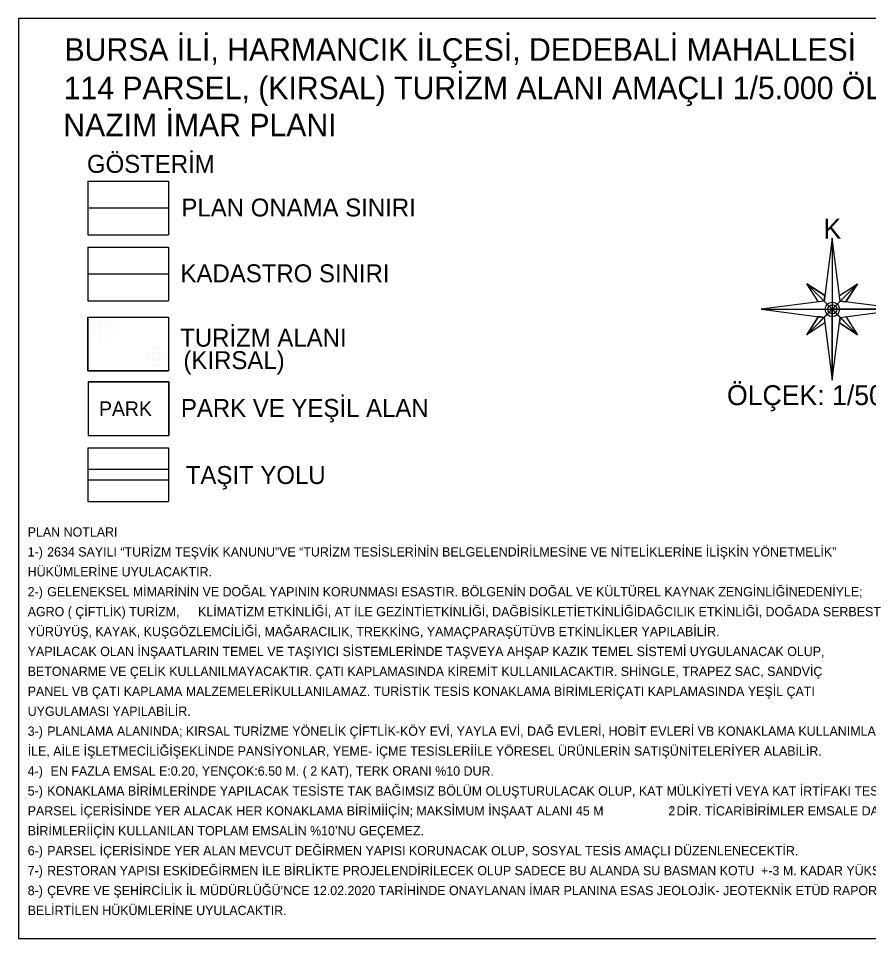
# Model space of a CAD drawing. Extents: x 415376 to 421084, y 4391163 to 4393878.
# Drawn here: x 416870 to 417511, y 4392614 to 4393307 of the extents above; entities that cross this region are included whole.
import ezdxf

# ---------------------------------------------------------------- set-up
doc = ezdxf.new("R2010")
doc.units = 0
for name, color, linetype in [('KALDIRIM', 7, 'Continuous'), ('LEJAND', 7, 'Continuous'), ('PL_KiRSALTURIZM', 7, 'Continuous'), ('PL_PARK', 7, 'Continuous'), ('SN_PLAN_ONAMA', 7, 'Continuous'), ('TR_TURIZM', 7, 'Continuous'), ('Z_PARSEL_PL', 7, 'Continuous')]:
    doc.layers.add(name, color=color, linetype=linetype)

msp = doc.modelspace()

# ---------------------------------------------------------------- linework, layer by layer
at = {"layer": 'KALDIRIM'}
for p, q in [((416922.79, 4392967.19), (416938.59, 4392967.19)), ((416938.59, 4392967.19), (416983.35, 4392967.19)), ((416922.79, 4392959.19), (416939.04, 4392959.19)), ((416939.04, 4392959.19), (416983.35, 4392959.19))]:
    msp.add_line(p, q, dxfattribs=at)
at = {"layer": 'LEJAND'}
for p, q in [((417672.31, 4393306.66), (416870.43, 4393306.66)), ((416870.43, 4393306.66), (416870.43, 4392613.77)), ((416922.79, 4393184.05), (416922.79, 4393143.6)), ((416922.79, 4393184.05), (416983.46, 4393184.05)), ((416983.46, 4393184.05), (416983.46, 4393143.6)), ((416922.79, 4393143.6), (416983.46, 4393143.6)), ((417483.55, 4393141.18), (417483.55, 4393087.66)), ((417483.99, 4393141.76), (417483.99, 4393141.65)), ((416922.79, 4393134.44), (416983.46, 4393134.44)), ((416922.79, 4393134.44), (416922.79, 4393093.99)), ((416983.46, 4393134.44), (416983.46, 4393093.99)), ((417483.55, 4393087.66), (417464.38, 4393106.82)), ((417483.55, 4393087.66), (417502.71, 4393106.82)), ((416922.79, 4393093.99), (416983.46, 4393093.99)), ((417430.02, 4393087.66), (417483.55, 4393087.66)), ((417483.55, 4393087.66), (417464.38, 4393068.5)), ((417483.55, 4393087.66), (417483.55, 4393034.14)), ((417483.55, 4393087.66), (417502.71, 4393068.5)), ((417483.55, 4393087.66), (417537.07, 4393087.66)), ((416922.79, 4393081.78), (416922.79, 4393041.34)), ((416922.79, 4393081.78), (416983.46, 4393081.78)), ((416983.46, 4393081.78), (416983.46, 4393041.34)), ((416922.79, 4393041.34), (416983.46, 4393041.34)), ((416923.11, 4393033.04), (416923.11, 4392992.6)), ((416923.11, 4393033.04), (416983.78, 4393033.04)), ((416983.78, 4393033.04), (416983.78, 4392992.6)), ((416923.11, 4392992.6), (416983.78, 4392992.6)), ((416922.79, 4392983.38), (416922.79, 4392942.93)), ((416922.79, 4392983.38), (416983.46, 4392983.38)), ((416983.46, 4392983.38), (416983.46, 4392942.93)), ((416922.79, 4392942.93), (416983.46, 4392942.93)), ((416870.43, 4392613.77), (417672.31, 4392613.77))]:
    msp.add_line(p, q, dxfattribs=at)
for points in [[(417489.64, 4393093.76), (417483.55, 4393141.18), (417477.45, 4393093.76), (417430.02, 4393087.66), (417477.45, 4393081.56), (417483.55, 4393034.14), (417489.64, 4393081.56), (417537.07, 4393087.66)], [(417483.55, 4393141.18), (417483.55, 4393087.66), (417489.64, 4393093.76)], [(417464.38, 4393106.82), (417477.45, 4393093.76), (417477.99, 4393098)], [(417489.64, 4393093.76), (417493.89, 4393093.21), (417502.71, 4393106.82)], [(417477.45, 4393093.76), (417430.07, 4393087.66), (417483.55, 4393087.66)], [(417483.55, 4393087.66), (417477.45, 4393081.56), (417483.55, 4393034.14)], [(417483.55, 4393087.66), (417489.64, 4393081.56), (417537.07, 4393087.66)], [(417473.2, 4393082.11), (417464.38, 4393068.5), (417477.45, 4393081.56)], [(417489.64, 4393081.56), (417489.1, 4393077.32), (417502.71, 4393068.5)]]:
    msp.add_lwpolyline(points, close=True, dxfattribs=at)
for points in [[(417473.2, 4393093.21), (417464.38, 4393106.82), (417477.99, 4393098)], [(417489.1, 4393098), (417502.71, 4393106.82), (417493.89, 4393093.21)], [(417477.99, 4393077.32), (417464.38, 4393068.5), (417473.2, 4393082.11)], [(417493.89, 4393082.11), (417502.71, 4393068.5), (417489.1, 4393077.32)]]:
    msp.add_lwpolyline(points, dxfattribs=at)
for centre, radius in [((417483.64, 4393087.53), 5.42), ((417483.73, 4393087.62), 3.39)]:
    msp.add_circle(centre, radius, dxfattribs=at)
at = {"layer": 'PL_KiRSALTURIZM'}
msp.add_lwpolyline([(416983.46, 4393081.78), (416983.46, 4393041.34), (416922.79, 4393041.34), (416922.79, 4393081.78)], close=True, dxfattribs=at)
at = {"layer": 'PL_PARK'}
msp.add_lwpolyline([(416983.78, 4393033.04), (416923.11, 4393033.04), (416923.11, 4392992.6), (416983.78, 4392992.6), (416983.78, 4393033.04)], dxfattribs=at)
at = {"layer": 'SN_PLAN_ONAMA'}
msp.add_line((416923.8, 4393164.06), (416983.11, 4393164.06), dxfattribs=at)
at = {"layer": 'TR_TURIZM'}
for p, q in [((416932.06, 4393079.11), (416932.06, 4393079.11)), ((416936.56, 4393079.11), (416936.56, 4393079.11)), ((416927.56, 4393074.61), (416927.56, 4393074.61)), ((416932.06, 4393074.61), (416932.06, 4393074.61)), ((416936.56, 4393074.61), (416936.56, 4393074.61)), ((416941.06, 4393074.61), (416941.06, 4393074.61)), ((416927.56, 4393070.11), (416927.56, 4393070.11)), ((416932.06, 4393070.11), (416932.06, 4393070.11)), ((416932.06, 4393065.61), (416932.06, 4393065.61)), ((416936.56, 4393070.11), (416936.56, 4393070.11)), ((416936.56, 4393065.61), (416936.56, 4393065.61)), ((416941.06, 4393070.11), (416941.06, 4393070.11)), ((416972.48, 4393058.55), (416972.48, 4393058.55)), ((416976.98, 4393058.55), (416976.98, 4393058.55)), ((416967.98, 4393054.05), (416967.98, 4393054.05)), ((416972.48, 4393054.05), (416972.48, 4393054.05)), ((416976.98, 4393054.05), (416976.98, 4393054.05)), ((416981.48, 4393054.05), (416981.48, 4393054.05)), ((416967.98, 4393049.55), (416967.98, 4393049.55)), ((416972.48, 4393049.55), (416972.48, 4393049.55)), ((416972.48, 4393045.05), (416972.48, 4393045.05)), ((416976.98, 4393049.55), (416976.98, 4393049.55)), ((416976.98, 4393045.05), (416976.98, 4393045.05)), ((416981.48, 4393049.55), (416981.48, 4393049.55))]:
    msp.add_line(p, q, dxfattribs=at)
at = {"layer": 'Z_PARSEL_PL'}
msp.add_line((416922.79, 4393114.22), (416983.46, 4393114.22), dxfattribs=at)

# ---------------------------------------------------------------- texts
at = {"layer": 'LEJAND'}
for s, height, p in [('BURSA İLİ, HARMANCIK İLÇESİ, DEDEBALİ MAHALLESİ', 17, (416905.18, 4393274.75)), ('114 PARSEL, (KIRSAL) TURİZM ALANI AMAÇLI 1/5.000 ÖLÇEKLİ', 17, (416904.57, 4393245.84)), ('NAZIM İMAR PLANI', 17, (416904.28, 4393217.87)), ('GÖSTERİM', 13.5, (416922.08, 4393190.37)), ('PLAN ONAMA SINIRI', 13.5, (416993.26, 4393157.51)), ('K', 15, (417476.88, 4393140.88)), ('KADASTRO SINIRI ', 13.5, (416992.56, 4393107.97)), ('TURİZM ALANI', 13.5, (416992.33, 4393059.51)), ('(KIRSAL)', 13.5, (416994.78, 4393042.58)), ('ÖLÇEK: 1/5000', 15, (417404.26, 4393015.45)), ('PARK VE YEŞİL ALAN', 13.5, (416992.88, 4393006.57)), ('PARK', 10.935, (416931.17, 4393007.33)), ('TAŞIT YOLU', 13.5, (416996.56, 4392956.08)), ('PLAN NOTLARI', 7, (416877.44, 4392916.48)), ('1-) ', 7, (416877.44, 4392901.48)), ('2634 SAYILI “TURİZM TEŞVİK KANUNU”VE “TURİZM TESİSLERİNİN BELGELENDİRİLMESİNE VE NİTELİKLERİNE İLİŞKİN YÖNETMELİK”', 7, (416892.1, 4392901.48)), ('HÜKÜMLERİNE UYULACAKTIR.', 7, (416877.44, 4392886.48)), ('2-)', 7, (416877.44, 4392871.48)), (' GELENEKSEL MİMARİNİN VE DOĞAL YAPININ KORUNMASI ESASTIR. BÖLGENİN DOĞAL VE KÜLTÜREL KAYNAK ZENGİNLİĞİNEDENİYLE; ', 7, (416889.52, 4392871.48)), ('AGRO ( ÇİFTLİK) TURİZM,', 7, (416877.44, 4392856.48)), ('KLİMATİZM ETKİNLİĞİ, AT İLE GEZİNTİETKİNLİĞİ, DAĞBİSİKLETİETKİNLİĞİDAĞCILIK ETKİNLİĞİ, DOĞADA SERBEST', 7, (417005.77, 4392856.48)), ('YÜRÜYÜŞ, KAYAK, KUŞGÖZLEMCİLİĞİ, MAĞARACILIK, TREKKİNG, YAMAÇPARAŞÜTÜVB ETKİNLİKLER YAPILABİLİR. ', 7, (416877.44, 4392841.48)), ('YAPILACAK OLAN İNŞAATLARIN TEMEL VE TAŞIYICI SİSTEMLERİNDE TAŞVEYA AHŞAP KAZIK TEMEL SİSTEMİ UYGULANACAK OLUP, ', 7, (416877.44, 4392826.48)), ('BETONARME VE ÇELİK KULLANILMAYACAKTIR. ÇATI KAPLAMASINDA KİREMİT KULLANILACAKTIR. SHİNGLE, TRAPEZ SAC, SANDVİÇ ', 7, (416877.44, 4392811.48)), ('PANEL VB ÇATI KAPLAMA MALZEMELERİKULLANILAMAZ. TURİSTİK TESİS KONAKLAMA BİRİMLERİÇATI KAPLAMASINDA YEŞİL ÇATI ', 7, (416877.44, 4392796.48)), ('UYGULAMASI YAPILABİLİR. ', 7, (416877.44, 4392781.48)), ('3-)', 7, (416877.44, 4392766.48)), (' PLANLAMA ALANINDA; KIRSAL TURİZME YÖNELİK ÇİFTLİK-KÖY EVİ, YAYLA EVİ, DAĞ EVLERİ, HOBİT EVLERİ VB KONAKLAMA KULLANIMLARI ', 7, (416889.52, 4392766.48)), ('İLE, AİLE İŞLETMECİLİĞİŞEKLİNDE PANSİYONLAR, YEME- İÇME TESİSLERİİLE YÖRESEL ÜRÜNLERİN SATIŞÜNİTELERİYER ALABİLİR. ', 7, (416877.44, 4392751.48)), ('4-)', 7, (416877.44, 4392736.48)), ('  EN FAZLA EMSAL E:0.20, YENÇOK:6.50 M. ( 2 KAT), TERK ORANI %10 DUR.', 7, (416889.52, 4392736.48)), ('5-)', 7, (416877.44, 4392721.48)), (' KONAKLAMA BİRİMLERİNDE YAPILACAK TESİSTE TAK BAĞIMSIZ BÖLÜM OLUŞTURULACAK OLUP, KAT MÜLKİYETİ VEYA KAT İRTİFAKI TESİS EDİLEMEZ. ', 7, (416889.52, 4392721.48)), ('PARSEL İÇERİSİNDE YER ALACAK HER KONAKLAMA BİRİMİİÇİN; MAKSİMUM İNŞAAT ALANI 45 M', 7, (416877.44, 4392706.48)), ('2', 7, (417360.07, 4392706.48)), ('’ DİR. TİCARİBİRİMLER EMSALE DAHİL OLUP, KONAKLAMA ', 7, (417361.62, 4392706.48)), ('BİRİMLERİİÇİN KULLANILAN TOPLAM EMSALİN %10’NU GEÇEMEZ.', 7, (416877.44, 4392691.48)), ('6-)', 7, (416877.44, 4392676.48)), (' PARSEL İÇERİSİNDE YER ALAN MEVCUT DEĞİRMEN YAPISI KORUNACAK OLUP, SOSYAL TESİS AMAÇLI DÜZENLENECEKTİR.', 7, (416889.52, 4392676.48)), ('RESTORAN YAPISI ESKİDEĞİRMEN İLE BİRLİKTE PROJELENDİRİLECEK OLUP SADECE BU ALANDA SU BASMAN KOTU  +-3 M. KADAR YÜKSELTİLEBİLİR.', 7, (416892.1, 4392661.48)), ('7-) ', 7, (416877.44, 4392661.48)), ('8-) ', 7, (416877.44, 4392646.48)), ('ÇEVRE VE ŞEHİRCİLİK İL MÜDÜRLÜĞÜ’NCE 12.02.2020 TARİHİNDE ONAYLANAN İMAR PLANINA ESAS JEOLOJİK- JEOTEKNİK ETÜD RAPORUNDA ', 7, (416892.1, 4392646.48)), ('BELİRTİLEN HÜKÜMLERİNE UYULACAKTIR.', 7, (416877.44, 4392631.48))]:
    msp.add_text(s, height=height, dxfattribs=at).set_placement(p)

doc.saveas('drawing.dxf')
